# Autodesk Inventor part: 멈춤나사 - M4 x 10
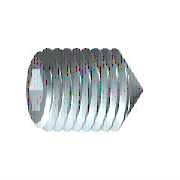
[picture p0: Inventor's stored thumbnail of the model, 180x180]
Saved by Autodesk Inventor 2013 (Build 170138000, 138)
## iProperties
Created: 2012-02
Part Number: 멈춤나사 - M4 x 10
Material: 강철, 연강
Description: 6각 소켓 머리 없는 멈춤 나사
Document SubType Name: Modeling
Standard: KS B 1028
Designer: mduedu
Standards Organization: KS
Language: ko-KR
Size Designation: 원추점 M4x10
Categories: <MemberInstance><Categories><Category DisplayName="조임쇠" InternalName="e4da775c-781d-43d5-af7c-5136215cf5a6" Mnemonic="FSTN"><Category DisplayName="볼트" InternalN
Density: 7.86 g/cm^3
Mass: 0.792069 g
Surface Area: 1.48192 cm^2
Volume: 0.100772 cm^3
Author: mduedu
IsCustomPart: 1
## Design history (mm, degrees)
sketch "스케치1"
  geometry: L1 (0, 0)-(6.833, 0); L2 (10, 1.155)-(10, 2); L3 (10, 2)-(0, 2); L4 (10, 1.155)-(7.5, 1.155); L5 (7.5, 1.155)-(6.833, 0); L6 (0, -0.4)-(0, 2.4) reference; L7 (0, 2)-(0, 0)
  constraints: 13 end point, 3 parallel, 1 collinear, 1 perpendicular, 1 point on line
  dimensions: "d0" = 2.5 distance of L2.start L4.end (= INTI); "d1" = 60 deg angle of L5 L1; "d2" = 4 diameter of L3 L1 (= NND); "d3" = 2.3094 diameter of L4 L1 (= 1.1547 x SW); "d5" = 10 distance from line of L2 L3.end (= NLG)
revolve "본체" sketch "스케치1" stored, may be unused: angle "d6" = 90 deg
sketch "스케치2"
  geometry: L1 (-0.577, 1)-(0.577, 1); L2 (0.577, 1)-(1.155, 0); L3 (1.155, 0)-(0.577, -1); L4 (0.577, -1)-(-0.577, -1); L5 (-0.577, -1)-(-1.155, 0); L6 (-1.155, 0)-(-0.577, 1); 3 further points
  constraints: 12 end point, 1 coincident, 1 horizontal, 13 other
extrude "슬롯" join sketch "스케치2" taper "d7" = 0 deg; stored distance "d21" = 10
workaxis "Work Axis1"
workplane "Work Plane1"
sketch "스케치4"
  geometry: L1 (-5, 0.2)-(-3.2, 2) reference; L2 (-5, -0.2)-(-3.2, -2) reference; L3 (-3.2, 2)-(-5.2, 0); L4 (-3.2, -2)-(-5.2, 0); 2 further points
  constraints: 4 end point, 2 collinear, 1 coincident
body "Solid1"
feature "스레드" dims "d12" = 10 (= NLG), "d13" = 0
chamfer "모따기1" distance "d8" = 1.8 (computed from NND, SPD, FAWI); stored, may be unused: angle "d9" = 45 deg (= FAWI), second distance "d34" = 1.8 (computed from NND, SPD, FAWI)
chamfer "모따기2" distance "d10" = 0.42941 (= -0.5 x GD1 + 0.5 x NND); stored, may be unused: angle "d11" = 45 deg (= FAWI), second distance "d35" = 0.42941 (= -0.5 x GD1 + 0.5 x NND)
other parameters: "NND" = 4 [user parameter; used in 5 equation terms], "NLG" = 10 [user parameter; used in 2 equation terms], "INTI" = 2.5 [user parameter; used in 1 equation term], "FAWI" = 45 deg [user parameter; used in 4 equation terms], "SW" = 2 [user parameter; used in 2 equation terms], "GD1" = 3.14117 (= THREADDIA - 1.2269 x PTC) [user parameter; used in 2 equation terms], "d4" = 0, "FAWI1" = 45 deg [user parameter], "SPD" = 0.4 [user parameter; used in 2 equation terms], "d36" = 0, "d37" = 0, "GUL" = 0.42941 (= 0.61345 x PTC) [user parameter], "TPU" = 14.28571 (computed from PTC) [user parameter], "TOA" = 30 deg [user parameter], "THREADDIA" = 4 [user parameter; used in 1 equation term], "PTC" = 0.7 [user parameter; used in 4 equation terms], "GAL" = 0.42941 (= 0.61345 x PTC) [user parameter], "E0" = 2.31 (= 1.155 x SW) [user parameter]
